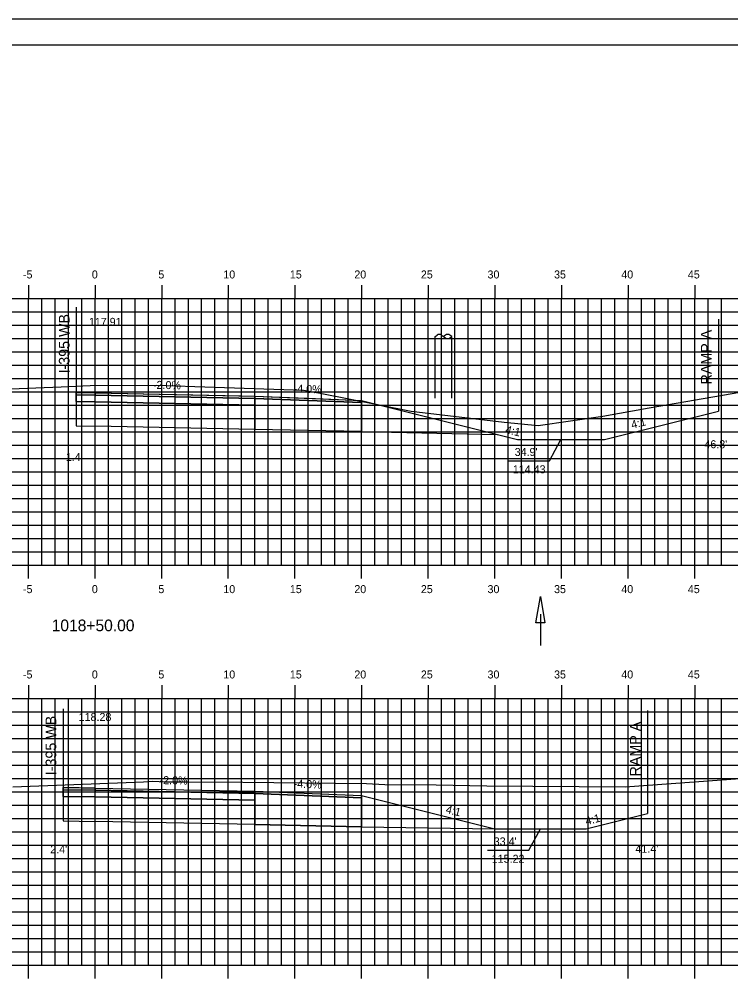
# Model space of a CAD drawing. Extents: x 853512 to 853684, y 365624 to 365734.
# Drawn here: x 853589.9 to 853643.3, y 365661.8 to 365734 of the extents above; entities that cross this region are included whole.
import ezdxf

# ---------------------------------------------------------------- set-up
doc = ezdxf.new("R2010")
doc.units = 0
for name, color, linetype in [('ANNOTATION', 7, 'Continuous'), ('BORDER', 7, 'Continuous'), ('D_Drainage_Ditch_Line', 7, 'Continuous'), ('D_Roadway_Centerline', 7, 'Continuous'), ('D_Roadway_Centerline_Text', 7, 'Continuous'), ('D_Roadway_Edge_Shoulder', 7, 'Continuous'), ('D_Roadway_Edge_TW', 7, 'Continuous'), ('D_Roadway_FinishedGrade', 7, 'Continuous'), ('D_Roadway_Pavement', 7, 'Continuous'), ('D_Roadway_SubGrade', 7, 'Continuous'), ('D_Text_Standard', 7, 'Continuous'), ('Default', 7, 'Continuous'), ('H_V ANNOTATION', 7, 'Continuous'), ('M_Roadway_Centerline', 7, 'Continuous'), ('MAJOR', 7, 'Continuous'), ('MINOR', 7, 'Continuous'), ('PLOT BOUNDARY', 7, 'Continuous'), ('S_Roadway_Centerline', 7, 'Continuous'), ('S_Utilities_Pole_StreetLight', 7, 'Continuous')]:
    doc.layers.add(name, color=color, linetype=linetype)

msp = doc.modelspace()

# ---------------------------------------------------------------- linework, layer by layer
at = {"layer": 'ANNOTATION'}
for points in [[(853626.554, 365700.852), (853629.664, 365700.852), (853630.529, 365702.457)], [(853625.019, 365671.642), (853628.129, 365671.642), (853628.994, 365673.247)]]:
    msp.add_lwpolyline(points, dxfattribs=at)
at = {"layer": 'BORDER'}
msp.add_lwpolyline([(853520.575, 365627.027), (853680.575, 365627.027), (853680.575, 365732.027), (853520.575, 365732.027)], close=True, dxfattribs=at)
at = {"layer": 'D_Drainage_Ditch_Line'}
msp.add_line((853628.988, 365689.36), (853628.987, 365687.011), dxfattribs=at)
msp.add_lwpolyline([(853629.316, 365688.704), (853628.659, 365688.704), (853628.987, 365690.672)], close=True, dxfattribs=at)
at = {"layer": 'D_Roadway_Centerline'}
for p, q in [((853615.574, 365703.04), (853625.748, 365702.836)), ((853627.266, 365702.457), (853633.791, 365702.457))]:
    msp.add_line(p, q, dxfattribs=at)
for points in [[(853594.167, 365705.968), (853595.574, 365705.94), (853606.576, 365705.72), (853607.575, 365705.7), (853612.118, 365705.518), (853615.574, 365705.38)], [(853615.574, 365705.38), (853619.574, 365704.38), (853627.266, 365702.457)], [(853633.791, 365702.457), (853642.343, 365704.586)], [(853593.171, 365676.352), (853593.173, 365676.352), (853594.609, 365676.323), (853595.575, 365676.304), (853607.571, 365676.064), (853607.575, 365676.064), (853615.573, 365675.744), (853615.574, 365675.744)], [(853615.574, 365675.744), (853619.574, 365674.744), (853625.562, 365673.247)], [(853632.426, 365673.247), (853637.018, 365674.39)], [(853615.574, 365673.404), (853607.574, 365673.564), (853615.574, 365673.404)], [(853615.574, 365673.404), (853625.562, 365673.247), (853632.426, 365673.247)]]:
    msp.add_lwpolyline(points, dxfattribs=at)
at = {"layer": 'D_Roadway_Edge_Shoulder'}
for points in [[(853595.574, 365705.94), (853594.167, 365705.968), (853594.167, 365705.801), (853595.574, 365705.773)], [(853607.575, 365705.7), (853615.574, 365705.38), (853615.574, 365705.213), (853607.575, 365705.533)], [(853595.574, 365676.304), (853593.171, 365676.352), (853593.171, 365676.185), (853595.574, 365676.137)], [(853607.574, 365676.064), (853615.574, 365675.744), (853615.574, 365675.577), (853607.574, 365675.897)]]:
    msp.add_lwpolyline(points, close=True, dxfattribs=at)
at = {"layer": 'D_Roadway_Edge_TW'}
for points in [[(853595.574, 365705.94), (853607.575, 365705.7), (853607.575, 365705.533), (853595.574, 365705.773)], [(853595.574, 365676.304), (853607.574, 365676.064), (853607.574, 365675.897), (853595.574, 365676.137)]]:
    msp.add_lwpolyline(points, close=True, dxfattribs=at)
for points in [[(853607.575, 365705.7), (853607.575, 365705.533)], [(853607.574, 365676.064), (853607.574, 365675.897)]]:
    msp.add_lwpolyline(points, dxfattribs=at)
at = {"layer": 'D_Roadway_FinishedGrade'}
for p, q in [((853594.167, 365705.968), (853594.167, 365705.718)), ((853595.574, 365705.94), (853595.574, 365705.69)), ((853607.575, 365705.7), (853607.575, 365705.45)), ((853615.574, 365705.38), (853615.574, 365705.13)), ((853593.171, 365676.352), (853593.171, 365676.102)), ((853595.574, 365676.304), (853595.574, 365676.054)), ((853607.574, 365676.064), (853607.574, 365675.814)), ((853615.574, 365675.744), (853615.574, 365675.494))]:
    msp.add_line(p, q, dxfattribs=at)
at = {"layer": 'D_Roadway_Pavement'}
for points in [[(853595.574, 365705.773), (853594.167, 365705.801), (853594.167, 365705.301), (853595.574, 365705.273)], [(853595.574, 365705.773), (853607.575, 365705.533), (853607.575, 365705.033), (853595.574, 365705.273)], [(853595.574, 365676.137), (853593.171, 365676.185), (853593.171, 365675.685), (853595.574, 365675.637)], [(853595.574, 365676.137), (853607.574, 365675.897), (853607.574, 365675.397), (853595.574, 365675.637)]]:
    msp.add_lwpolyline(points, close=True, dxfattribs=at)
for points in [[(853607.575, 365705.533), (853607.575, 365705.033)], [(853607.575, 365705.533), (853607.575, 365705.033)], [(853607.574, 365675.897), (853607.574, 365675.397)], [(853607.574, 365675.897), (853607.574, 365675.397)]]:
    msp.add_lwpolyline(points, dxfattribs=at)
at = {"layer": 'D_Roadway_SubGrade'}
for p, q in [((853594.167, 365712.379), (853594.167, 365703.468)), ((853642.343, 365711.479), (853642.343, 365704.586)), ((853593.171, 365682.256), (853593.171, 365673.852)), ((853637.018, 365682.12), (853637.018, 365674.39))]:
    msp.add_line(p, q, dxfattribs=at)
for points in [[(853595.574, 365705.273), (853594.167, 365705.301), (853594.167, 365705.801), (853594.167, 365705.968), (853594.167, 365703.468), (853595.574, 365703.44)], [(853595.574, 365705.273), (853607.575, 365705.033), (853607.575, 365703.2), (853595.574, 365703.44)], [(853607.575, 365705.033), (853607.575, 365705.533), (853615.574, 365705.213), (853615.574, 365705.38), (853615.574, 365703.04), (853607.575, 365703.2)], [(853595.574, 365675.637), (853593.171, 365675.685), (853593.171, 365676.185), (853593.171, 365676.352), (853593.171, 365673.852), (853595.574, 365673.804)], [(853595.574, 365675.637), (853607.574, 365675.397), (853607.574, 365673.564), (853595.574, 365673.804)], [(853607.574, 365675.397), (853607.574, 365675.897), (853615.574, 365675.577), (853615.574, 365675.744), (853615.574, 365673.404), (853607.574, 365673.564)]]:
    msp.add_lwpolyline(points, close=True, dxfattribs=at)
for points in [[(853607.575, 365705.033), (853607.575, 365703.2)], [(853607.574, 365675.397), (853607.574, 365673.564)]]:
    msp.add_lwpolyline(points, dxfattribs=at)
at = {"layer": 'Default'}
for points in [[(853615.574, 365705.38), (853619.574, 365704.38), (853627.266, 365702.457)], [(853615.574, 365675.744), (853619.574, 365674.744), (853625.562, 365673.247)]]:
    msp.add_lwpolyline(points, dxfattribs=at)
at = {"layer": 'MAJOR'}
for p, q in [((853590.575, 365714.029), (853590.575, 365713.027)), ((853595.575, 365714.029), (853595.575, 365713.027)), ((853600.575, 365714.029), (853600.575, 365713.027)), ((853605.575, 365714.029), (853605.575, 365713.027)), ((853610.575, 365714.029), (853610.575, 365713.027)), ((853615.575, 365714.029), (853615.575, 365713.027)), ((853620.575, 365714.029), (853620.575, 365713.027)), ((853625.575, 365714.029), (853625.575, 365713.027)), ((853630.575, 365714.029), (853630.575, 365713.027)), ((853635.575, 365714.029), (853635.575, 365713.027)), ((853640.575, 365714.029), (853640.575, 365713.027)), ((853525.575, 365713.027), (853665.575, 365713.027)), ((853525.575, 365713.027), (853665.575, 365713.027)), ((853590.575, 365693.027), (853590.575, 365713.027)), ((853595.575, 365693.027), (853595.575, 365713.027)), ((853600.575, 365693.027), (853600.575, 365713.027)), ((853605.575, 365693.027), (853605.575, 365713.027)), ((853610.575, 365693.027), (853610.575, 365713.027)), ((853615.575, 365693.027), (853615.575, 365713.027)), ((853620.575, 365693.027), (853620.575, 365713.027)), ((853625.575, 365693.027), (853625.575, 365713.027)), ((853630.575, 365693.027), (853630.575, 365713.027)), ((853635.575, 365693.027), (853635.575, 365713.027)), ((853640.575, 365693.027), (853640.575, 365713.027)), ((853525.575, 365708.027), (853665.575, 365708.027)), ((853525.575, 365703.027), (853665.575, 365703.027)), ((853525.575, 365698.027), (853665.575, 365698.027)), ((853525.575, 365693.027), (853665.575, 365693.027)), ((853525.575, 365693.027), (853665.575, 365693.027)), ((853590.575, 365692.025), (853590.575, 365693.027)), ((853595.575, 365692.025), (853595.575, 365693.027)), ((853600.575, 365692.025), (853600.575, 365693.027)), ((853605.575, 365692.025), (853605.575, 365693.027)), ((853610.575, 365692.025), (853610.575, 365693.027)), ((853615.575, 365692.025), (853615.575, 365693.027)), ((853620.575, 365692.025), (853620.575, 365693.027)), ((853625.575, 365692.025), (853625.575, 365693.027)), ((853630.575, 365692.025), (853630.575, 365693.027)), ((853635.575, 365692.025), (853635.575, 365693.027)), ((853640.575, 365692.025), (853640.575, 365693.027)), ((853590.575, 365684.029), (853590.575, 365683.027)), ((853595.575, 365684.029), (853595.575, 365683.027)), ((853600.575, 365684.029), (853600.575, 365683.027)), ((853605.575, 365684.029), (853605.575, 365683.027)), ((853610.575, 365684.029), (853610.575, 365683.027)), ((853615.575, 365684.029), (853615.575, 365683.027)), ((853620.575, 365684.029), (853620.575, 365683.027)), ((853625.575, 365684.029), (853625.575, 365683.027)), ((853630.575, 365684.029), (853630.575, 365683.027)), ((853635.575, 365684.029), (853635.575, 365683.027)), ((853640.575, 365684.029), (853640.575, 365683.027)), ((853525.575, 365683.027), (853665.575, 365683.027)), ((853525.575, 365683.027), (853665.575, 365683.027)), ((853590.575, 365663.027), (853590.575, 365683.027)), ((853595.575, 365663.027), (853595.575, 365683.027)), ((853600.575, 365663.027), (853600.575, 365683.027)), ((853605.575, 365663.027), (853605.575, 365683.027)), ((853610.575, 365663.027), (853610.575, 365683.027)), ((853615.575, 365663.027), (853615.575, 365683.027)), ((853620.575, 365663.027), (853620.575, 365683.027)), ((853625.575, 365663.027), (853625.575, 365683.027)), ((853630.575, 365663.027), (853630.575, 365683.027)), ((853635.575, 365663.027), (853635.575, 365683.027)), ((853640.575, 365663.027), (853640.575, 365683.027)), ((853525.575, 365678.027), (853665.575, 365678.027)), ((853525.575, 365673.027), (853665.575, 365673.027)), ((853525.575, 365668.027), (853665.575, 365668.027)), ((853525.575, 365663.027), (853665.575, 365663.027)), ((853525.575, 365663.027), (853665.575, 365663.027)), ((853590.575, 365662.025), (853590.575, 365663.027)), ((853595.575, 365662.025), (853595.575, 365663.027)), ((853600.575, 365662.025), (853600.575, 365663.027)), ((853605.575, 365662.025), (853605.575, 365663.027)), ((853610.575, 365662.025), (853610.575, 365663.027)), ((853615.575, 365662.025), (853615.575, 365663.027)), ((853620.575, 365662.025), (853620.575, 365663.027)), ((853625.575, 365662.025), (853625.575, 365663.027)), ((853630.575, 365662.025), (853630.575, 365663.027)), ((853635.575, 365662.025), (853635.575, 365663.027)), ((853640.575, 365662.025), (853640.575, 365663.027))]:
    msp.add_line(p, q, dxfattribs=at)
at = {"layer": 'MINOR'}
for p, q in [((853591.575, 365693.027), (853591.575, 365713.027)), ((853592.575, 365693.027), (853592.575, 365713.027)), ((853593.575, 365693.027), (853593.575, 365713.027)), ((853594.575, 365693.027), (853594.575, 365713.027)), ((853596.575, 365693.027), (853596.575, 365713.027)), ((853597.575, 365693.027), (853597.575, 365713.027)), ((853598.575, 365693.027), (853598.575, 365713.027)), ((853599.575, 365693.027), (853599.575, 365713.027)), ((853601.575, 365693.027), (853601.575, 365713.027)), ((853602.575, 365693.027), (853602.575, 365713.027)), ((853603.575, 365693.027), (853603.575, 365713.027)), ((853604.575, 365693.027), (853604.575, 365713.027)), ((853606.575, 365693.027), (853606.575, 365713.027)), ((853607.575, 365693.027), (853607.575, 365713.027)), ((853608.575, 365693.027), (853608.575, 365713.027)), ((853609.575, 365693.027), (853609.575, 365713.027)), ((853611.575, 365693.027), (853611.575, 365713.027)), ((853612.575, 365693.027), (853612.575, 365713.027)), ((853613.575, 365693.027), (853613.575, 365713.027)), ((853614.575, 365693.027), (853614.575, 365713.027)), ((853616.575, 365693.027), (853616.575, 365713.027)), ((853617.575, 365693.027), (853617.575, 365713.027)), ((853618.575, 365693.027), (853618.575, 365713.027)), ((853619.575, 365693.027), (853619.575, 365713.027)), ((853621.575, 365693.027), (853621.575, 365713.027)), ((853622.575, 365693.027), (853622.575, 365713.027)), ((853623.575, 365693.027), (853623.575, 365713.027)), ((853624.575, 365693.027), (853624.575, 365713.027)), ((853626.575, 365693.027), (853626.575, 365713.027)), ((853627.575, 365693.027), (853627.575, 365713.027)), ((853628.575, 365693.027), (853628.575, 365713.027)), ((853629.575, 365693.027), (853629.575, 365713.027)), ((853631.575, 365693.027), (853631.575, 365713.027)), ((853632.575, 365693.027), (853632.575, 365713.027)), ((853633.575, 365693.027), (853633.575, 365713.027)), ((853634.575, 365693.027), (853634.575, 365713.027)), ((853636.575, 365693.027), (853636.575, 365713.027)), ((853637.575, 365693.027), (853637.575, 365713.027)), ((853638.575, 365693.027), (853638.575, 365713.027)), ((853639.575, 365693.027), (853639.575, 365713.027)), ((853641.575, 365693.027), (853641.575, 365713.027)), ((853642.575, 365693.027), (853642.575, 365713.027)), ((853525.575, 365712.027), (853665.575, 365712.027)), ((853525.575, 365711.027), (853665.575, 365711.027)), ((853525.575, 365710.027), (853665.575, 365710.027)), ((853525.575, 365709.027), (853665.575, 365709.027)), ((853525.575, 365707.027), (853665.575, 365707.027)), ((853525.575, 365706.027), (853665.575, 365706.027)), ((853525.575, 365705.027), (853665.575, 365705.027)), ((853525.575, 365704.027), (853665.575, 365704.027)), ((853525.575, 365702.027), (853665.575, 365702.027)), ((853525.575, 365701.027), (853665.575, 365701.027)), ((853525.575, 365700.027), (853665.575, 365700.027)), ((853525.575, 365699.027), (853665.575, 365699.027)), ((853525.575, 365697.027), (853665.575, 365697.027)), ((853525.575, 365696.027), (853665.575, 365696.027)), ((853525.575, 365695.027), (853665.575, 365695.027)), ((853525.575, 365694.027), (853665.575, 365694.027)), ((853591.575, 365663.027), (853591.575, 365683.027)), ((853592.575, 365663.027), (853592.575, 365683.027)), ((853593.575, 365663.027), (853593.575, 365683.027)), ((853594.575, 365663.027), (853594.575, 365683.027)), ((853596.575, 365663.027), (853596.575, 365683.027)), ((853597.575, 365663.027), (853597.575, 365683.027)), ((853598.575, 365663.027), (853598.575, 365683.027)), ((853599.575, 365663.027), (853599.575, 365683.027)), ((853601.575, 365663.027), (853601.575, 365683.027)), ((853602.575, 365663.027), (853602.575, 365683.027)), ((853603.575, 365663.027), (853603.575, 365683.027)), ((853604.575, 365663.027), (853604.575, 365683.027)), ((853606.575, 365663.027), (853606.575, 365683.027)), ((853607.575, 365663.027), (853607.575, 365683.027)), ((853608.575, 365663.027), (853608.575, 365683.027)), ((853609.575, 365663.027), (853609.575, 365683.027)), ((853611.575, 365663.027), (853611.575, 365683.027)), ((853612.575, 365663.027), (853612.575, 365683.027)), ((853613.575, 365663.027), (853613.575, 365683.027)), ((853614.575, 365663.027), (853614.575, 365683.027)), ((853616.575, 365663.027), (853616.575, 365683.027)), ((853617.575, 365663.027), (853617.575, 365683.027)), ((853618.575, 365663.027), (853618.575, 365683.027)), ((853619.575, 365663.027), (853619.575, 365683.027)), ((853621.575, 365663.027), (853621.575, 365683.027)), ((853622.575, 365663.027), (853622.575, 365683.027)), ((853623.575, 365663.027), (853623.575, 365683.027)), ((853624.575, 365663.027), (853624.575, 365683.027)), ((853626.575, 365663.027), (853626.575, 365683.027)), ((853627.575, 365663.027), (853627.575, 365683.027)), ((853628.575, 365663.027), (853628.575, 365683.027)), ((853629.575, 365663.027), (853629.575, 365683.027)), ((853631.575, 365663.027), (853631.575, 365683.027)), ((853632.575, 365663.027), (853632.575, 365683.027)), ((853633.575, 365663.027), (853633.575, 365683.027)), ((853634.575, 365663.027), (853634.575, 365683.027)), ((853636.575, 365663.027), (853636.575, 365683.027)), ((853637.575, 365663.027), (853637.575, 365683.027)), ((853638.575, 365663.027), (853638.575, 365683.027)), ((853639.575, 365663.027), (853639.575, 365683.027)), ((853641.575, 365663.027), (853641.575, 365683.027)), ((853642.575, 365663.027), (853642.575, 365683.027)), ((853525.575, 365682.027), (853665.575, 365682.027)), ((853525.575, 365681.027), (853665.575, 365681.027)), ((853525.575, 365680.027), (853665.575, 365680.027)), ((853525.575, 365679.027), (853665.575, 365679.027)), ((853525.575, 365677.027), (853665.575, 365677.027)), ((853525.575, 365676.027), (853665.575, 365676.027)), ((853525.575, 365675.027), (853665.575, 365675.027)), ((853525.575, 365674.027), (853665.575, 365674.027)), ((853525.575, 365672.027), (853665.575, 365672.027)), ((853525.575, 365671.027), (853665.575, 365671.027)), ((853525.575, 365670.027), (853665.575, 365670.027)), ((853525.575, 365669.027), (853665.575, 365669.027)), ((853525.575, 365667.027), (853665.575, 365667.027)), ((853525.575, 365666.027), (853665.575, 365666.027)), ((853525.575, 365665.027), (853665.575, 365665.027)), ((853525.575, 365664.027), (853665.575, 365664.027))]:
    msp.add_line(p, q, dxfattribs=at)
at = {"layer": 'PLOT BOUNDARY'}
msp.add_lwpolyline([(853512.481, 365623.968), (853682.481, 365623.968), (853682.481, 365733.968), (853512.481, 365733.968)], close=True, dxfattribs=at)
at = {"layer": 'S_Roadway_Centerline'}
for points in [[(853584.159, 365706.037), (853593.037, 365706.394), (853595.213, 365706.498), (853600.208, 365706.521), (853603.056, 365706.435), (853611.204, 365706.146), (853612.332, 365705.938), (853619.285, 365704.571), (853626.269, 365703.743), (853628.823, 365703.496), (853633.667, 365704.187), (853637.151, 365704.825), (853649.447, 365706.952), (853654.675, 365707.863), (853654.79, 365707.86), (853655.281, 365707.863), (853655.479, 365707.86), (853656.357, 365707.841), (853657.066, 365707.809), (853658.062, 365707.803), (853660.567, 365707.714), (853665.575, 365707.438)], [(853589.415, 365676.405), (853599.207, 365676.766), (853599.921, 365676.825), (853600.862, 365676.773), (853602.595, 365676.77), (853606.652, 365676.743), (853615.951, 365676.647), (853617.308, 365676.575), (853621.165, 365676.549), (853624.969, 365676.485), (853635.352, 365676.394), (853645.716, 365677.143), (853647.446, 365677.228), (853648.142, 365677.273), (853649.721, 365677.423), (853651.167, 365677.428), (853657.245, 365677.407), (853659.739, 365677.437), (853661.931, 365677.354), (853661.978, 365677.397), (853665.575, 365677.181)]]:
    msp.add_lwpolyline(points, dxfattribs=at)
at = {"layer": 'S_Utilities_Pole_StreetLight'}
for p, q in [((853621.095, 365705.555), (853621.092, 365710.174)), ((853621.095, 365710.174), (853621.251, 365710.284)), ((853621.564, 365710.284), (853621.72, 365710.174)), ((853621.877, 365710.284), (853621.72, 365710.174)), ((853621.72, 365710.174), (853621.877, 365710.063)), ((853622.345, 365710.174), (853622.189, 365710.284)), ((853622.189, 365710.063), (853622.345, 365710.174)), ((853622.345, 365705.555), (853622.342, 365710.174))]:
    msp.add_line(p, q, dxfattribs=at)
for centre, start, end in [((853621.408, 365710.064), 90, 125.26439), ((853621.408, 365710.064), 54.73561, 90), ((853622.033, 365710.064), 90, 125.26439), ((853622.033, 365710.285), 234.73561, 270), ((853622.033, 365710.064), 54.73561, 90), ((853622.033, 365710.285), 270, 305.26439)]:
    msp.add_arc(centre, 0.271, start, end, dxfattribs=at)

# ---------------------------------------------------------------- texts
at = {"layer": 'ANNOTATION'}
for s, height, rotation, p in [('I-395 WB', 0.8, 90, (853593.66, 365707.401)), ('RAMP A', 0.8, 90, (853641.836, 365706.578)), ('-2.0%', 0.6, 358.85429, (853599.918, 365706.253)), ('-4.0%', 0.6, 357.70912, (853610.47, 365705.985)), ('4:1', 0.6, 13.98, (853635.878, 365703.251)), ('4:1', 0.6, 345.96376, (853626.325, 365702.941)), ("34.9' ", 0.6, 360, (853627.061, 365701.215)), ('114.43', 0.6, 360, (853626.922, 365699.915)), ('I-395 WB', 0.8, 90, (853592.664, 365677.27)), ('RAMP A', 0.8, 90, (853636.511, 365677.181)), ('-2.0%', 0.6, 358.85423, (853600.416, 365676.607)), ('-4.0%', 0.6, 357.70931, (853610.47, 365676.349)), ('4:1', 0.6, 345.96376, (853621.856, 365674.448)), ('4:1', 0.6, 13.98502, (853632.448, 365673.527)), ("33.4' ", 0.6, 360, (853625.489, 365672.005)), ('115.22', 0.6, 360, (853625.339, 365670.705))]:
    msp.add_text(s, height=height, rotation=rotation, dxfattribs=at).set_placement(p)
at = {"layer": 'D_Roadway_Centerline'}
for s, p in [('C', (853595.569, 365705.94)), ('L', (853595.574, 365705.933)), ('C', (853595.569, 365676.304)), ('L', (853595.574, 365676.296))]:
    msp.add_text(s, height=0.0146, dxfattribs=at).set_placement(p)
at = {"layer": 'D_Roadway_Centerline_Text'}
for s, p in [('117.91', (853595.112, 365710.972)), ('118.28', (853594.347, 365681.336))]:
    msp.add_text(s, height=0.6, dxfattribs=at).set_placement(p)
at = {"layer": 'D_Text_Standard'}
for s, p in [("46.8'", (853641.297, 365701.793)), ("1.4'", (853593.383, 365700.839)), ("2.4'", (853592.216, 365671.419)), ("41.4'", (853636.122, 365671.457))]:
    msp.add_text(s, height=0.6, dxfattribs=at).set_placement(p)
at = {"layer": 'H_V ANNOTATION'}
for s, height, p in [('-5', 0.6, (853590.165, 365714.527)), ('0', 0.6, (853595.334, 365714.527)), ('5', 0.6, (853600.326, 365714.527)), ('10', 0.6, (853605.2, 365714.527)), ('15', 0.6, (853610.192, 365714.527)), ('20', 0.6, (853615.029, 365714.527)), ('25', 0.6, (853620.021, 365714.527)), ('30', 0.6, (853625.023, 365714.527)), ('35', 0.6, (853630.015, 365714.527)), ('40', 0.6, (853635.061, 365714.527)), ('45', 0.6, (853640.053, 365714.527)), ('-5', 0.6, (853590.165, 365690.927)), ('0', 0.6, (853595.334, 365690.927)), ('5', 0.6, (853600.326, 365690.927)), ('10', 0.6, (853605.2, 365690.927)), ('15', 0.6, (853610.192, 365690.927)), ('20', 0.6, (853615.029, 365690.927)), ('25', 0.6, (853620.021, 365690.927)), ('30', 0.6, (853625.023, 365690.927)), ('35', 0.6, (853630.015, 365690.927)), ('40', 0.6, (853635.061, 365690.927)), ('45', 0.6, (853640.053, 365690.927)), ('1018+50.00', 0.875, (853592.321, 365688.07)), ('-5', 0.6, (853590.165, 365684.527)), ('0', 0.6, (853595.334, 365684.527)), ('5', 0.6, (853600.326, 365684.527)), ('10', 0.6, (853605.2, 365684.527)), ('15', 0.6, (853610.192, 365684.527)), ('20', 0.6, (853615.029, 365684.527)), ('25', 0.6, (853620.021, 365684.527)), ('30', 0.6, (853625.023, 365684.527)), ('35', 0.6, (853630.015, 365684.527)), ('40', 0.6, (853635.061, 365684.527)), ('45', 0.6, (853640.053, 365684.527))]:
    msp.add_text(s, height=height, dxfattribs=at).set_placement(p)
at = {"layer": 'M_Roadway_Centerline'}
for s, p in [('C', (853595.208, 365706.498)), ('L', (853595.213, 365706.49)), ('C', (853599.916, 365676.825)), ('L', (853599.921, 365676.818))]:
    msp.add_text(s, height=0.0146, dxfattribs=at).set_placement(p)

doc.saveas('drawing.dxf')
